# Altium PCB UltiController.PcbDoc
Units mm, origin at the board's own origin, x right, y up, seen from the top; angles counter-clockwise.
Board outline 170 x 47 mm, 2 copper layers (Top Layer, Bottom Layer), stack 1.586 mm thick; 131 components, 59 nets, 314 pads, 147 vias.
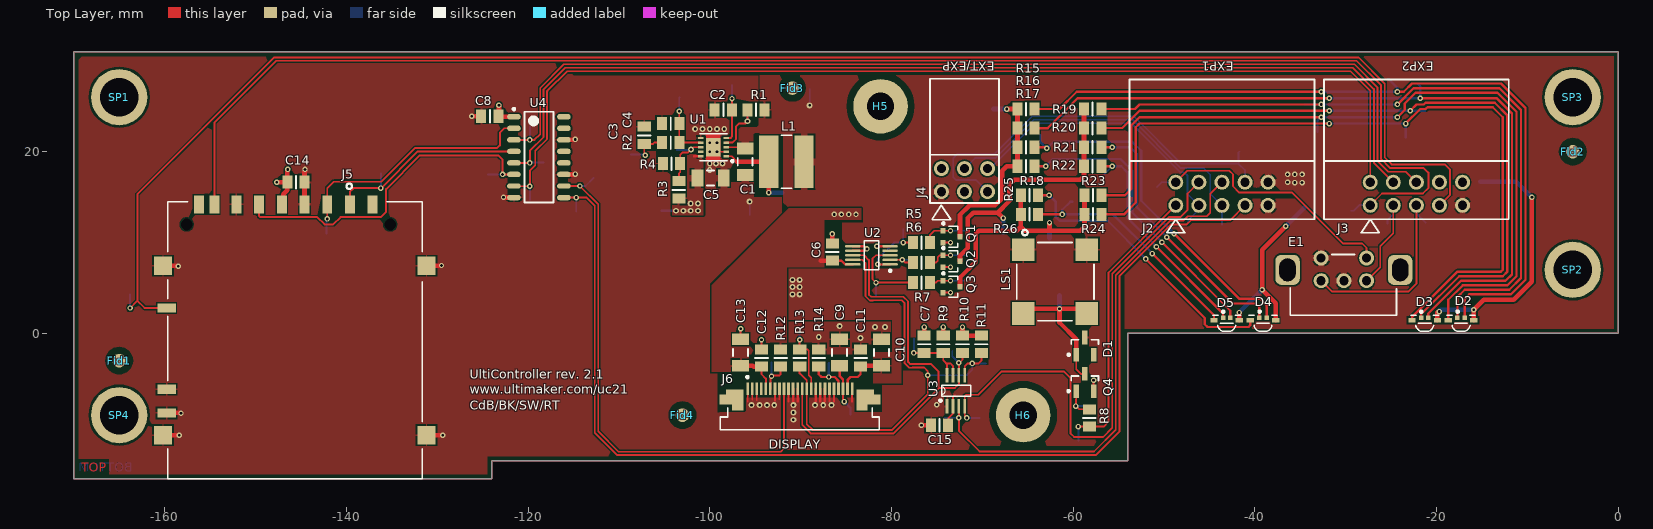
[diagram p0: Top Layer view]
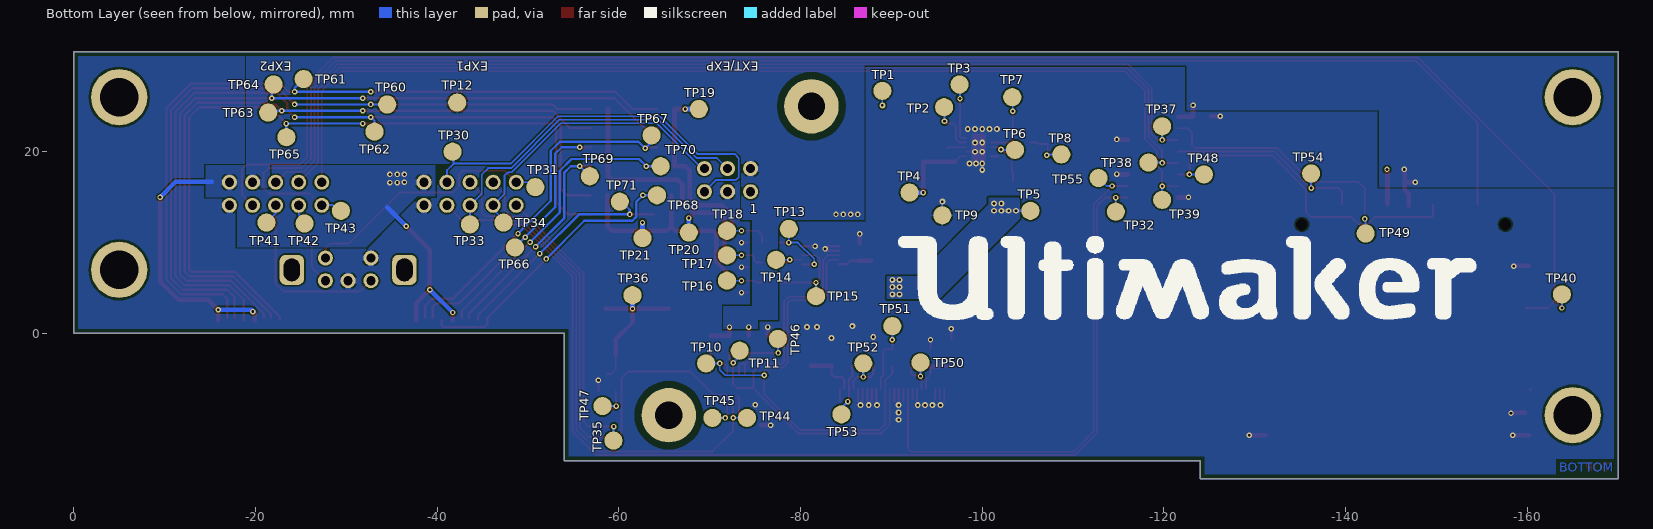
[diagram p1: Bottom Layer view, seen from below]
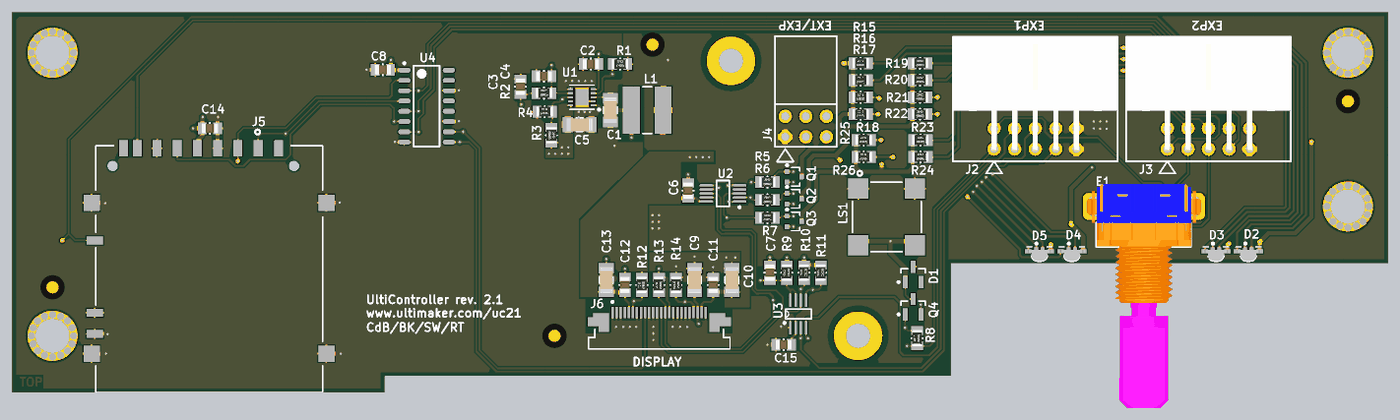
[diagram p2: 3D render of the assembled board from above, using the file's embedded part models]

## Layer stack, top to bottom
Top Layer: signal copper 0.018
Dielectric: core 1.55, FR-4, Dk 4.8
Bottom Layer: signal copper 0.018

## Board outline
-170,-16 -124,-16 -124,-14 -54,-14 -54,0 0,0 0,31 -170,31

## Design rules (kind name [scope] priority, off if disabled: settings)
AssemblyTestPointUsage [All] p1 off:
AssemblyTestpoint [All] p1: testpointundercomponent=FALSE minsize=1.016 maxsize=2.54 preferedsize=1.524 minholesize=0 maxholesize=1.016 preferedholesize=0.813 testpointgrid=0.025 usegrid=TRUE gridtolerance=0 allowsidetop=TRUE allowsidebottom=TRUE
Clearance "Clearance spacers" [(InComponent('SP1')) or (InComponent('SP2'))  or (InComponent('SP3')) or (InComponent('SP4'))] p1: gap=0.254
Clearance "Clearance fiduals" [(InComponent('Fid1'))or (InComponent('Fid2'))or  (InComponent('Fid3'))or  (InComponent('Fid4'))] p2: gap=0.762
Clearance "Clearance mounting holes" [(InComponent('H5')) or (InComponent('H6'))] p3: gap=0.762
Clearance Clearance-xPP-xTP-xTT [All] p4: gap=0.178
ComponentClearance [All] p1: gap=0.25 collisioncheckmode=3 verticalgap=0.25 showdistances=FALSE
DiffPairsRouting [All] p1: maxlimit=0.25 minlimit=0.25 mostfreqgap=0.25 maxuncoupledlength=12.5
FabricationTestPointUsage [All] p1 off: valid=0 allowmultiple=FALSE
Height [All] p1: minheight=0 maxheight=25 prefheight=12.5
HoleSize HoleSize-PTH [All] p1: absolutevalues=TRUE maxlimit=4.3 minlimit=0.25 maxpercent=80.000 minpercent=20.000
HoleToHoleClearance [All] p1: gap=0.15 allowstackedmicrovias=TRUE
MinimumAnnularRing "Minimum IAR  >0.45mm" [((ObjectKind = 'Pad') OR (ObjectKind = 'Via')) And (Layer = 'MultiLayer') And (HoleDiameter > AsMM(0.45))] p1: minimumring=0.25 // minimum inner annular ring for pads > 0.45mm finished hole size
MinimumAnnularRing "Minimum IAR <=0.45mm" [((ObjectKind = 'Pad') OR (ObjectKind = 'Via')) And (Layer = 'MultiLayer') And (HoleDiameter <= AsMM(0.45))] p2: minimumring=0.225 // minimum inner annular ring for pads <= 0.45mm finished hole size
MinimumSolderMaskSliver [All] p1: minsoldermaskwidth=0.1
PlaneClearance PlaneClearance-IPI [All] p1: clearance=0.4
PlaneConnect [All] p1: planeconnectstyle=Relief reliefexpansion=0.4 reliefentries=4 reliefconductorwidth=0.2 reliefairgap=0.2
PolygonConnect "PolygonConnect_ReliefConnect 20mil" [(InComponent('L1'))or (InComponent('C1'))or (InComponent('C5')) or (InComponent('J1'))or(InComponent('J2'))or (InComponent('J3'))or (InComponent('J4'))or (InComponent('E1'))] p1: connectstyle=Relief reliefconductorwidth=0.762 reliefentries=4 polygonreliefangle="90 Angle"
PolygonConnect PolygonConnect_Via [IsVia] p2: connectstyle=Direct reliefconductorwidth=0.254 reliefentries=4 polygonreliefangle="90 Angle"
PolygonConnect PolygonConnect-ReliefConnect [All] p3: connectstyle=Relief reliefconductorwidth=0.2 reliefentries=4 polygonreliefangle="90 Angle"
RoomDefinition Sheet2 [InComponentClass('Sheet2')] p1 off: confinementstyle=ConfineIn formatcopy=TRUE lockcomponents=FALSE outline 101.099,3.499 105.799,3.499 105.799,8.399 101.099,8.399
RoomDefinition Sheet1 [InComponentClass('Sheet1')] p2 off: confinementstyle=ConfineIn formatcopy=TRUE lockcomponents=FALSE outline 101.099,3.499 158.099,3.499 158.099,12.599 101.099,12.599
RoutingCorners [All] p1: cornerstyle=45-Degree minsetback=2.5 maxsetback=2.5
RoutingVias [All] p1: holewidth=0.3 width=0.6 viastyle="Through Hole" minholewidth=0.3 minwidth=0.6 maxholewidth=0.3 maxwidth=0.6
SilkToSilkClearance [All] p1: silktosilkclearance=0.2
SilkscreenOverComponentPads [IsPad] p1: minsilkscreentomaskgap=0.2
SolderMaskExpansion [All] p1: expansion=0.1
Width Width-xTW [All] p1: maxlimit=1.5 minlimit=0.15 preferedwidth=0.2
14 further rules are at their usual default settings.

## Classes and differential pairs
component class Sheet1: C1 C2 C3 C4 C5 C6 D2 D3 D4 D5 Fid1 Fid2 Fid3 Fid4 H2 H5 H6 L1 Q1 Q2 Q3 R1 R2 R3 R4 R5 R6 R7 R15 R16 R17 R18 R19 R20 R21 R22 R23 R24 R25 R26 SP1 SP2 SP3 SP4 TP1 TP2 TP3 TP4 TP5 TP6 TP7 TP8 TP9 TP10 TP11 TP12 TP13 TP14 TP15 TP16 TP17 TP18 TP19 TP20 TP21 TP60 TP61 TP62 TP63 TP64 TP65 TP66 TP67 TP68 TP69 TP70 TP71 U1 U2
component class Sheet2: C7 C8 C9 C10 C11 C12 C13 C14 C15 D1 E1 J2 J3 J4 J5 J6 LS1 Q4 R8 R9 R10 R11 R12 R13 R14 TP30 TP31 TP32 TP33 TP34 TP35 TP36 TP37 TP38 TP39 TP40 TP41 TP42 TP43 TP44 TP45 TP46 TP47 TP48 TP49 TP50 TP51 TP52 TP53 TP54 TP55 U3 U4

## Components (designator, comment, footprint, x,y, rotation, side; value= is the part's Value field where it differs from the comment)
C1 "4.7uF" "C1206 (3216)" -96.1,18.9 r90 top
C2 "10nF" "C0805 (2012)" -98.5,24.6 r0 top
C3 "2.2nF" "C0805 (2012)" -107.2,21.8 r270 top
C4 "15pF" "C0805 (2012)" -104.3,23.1 r0 top
C5 "10uF" "C1206 (3216)" -99.9,17.1 r180 top
C6 "100nF" "C0805 (2012)" -86.5,8.95 r90 top
C7 "10nF" "C0805 (2012)" -76.4,-1.2 r270 top
C8 "100nF" "C0805 (2012)" -124.2,23.9 r0 top
C9 "4.7uF" "C1206 (3216)" -85.7,-2.1 r90 top
C10 "10uF" "C1206 (3216)" -81.1,-2.1 r270 top
C11 "100nF" "C0805 (2012)" -83.4,-2.7 r270 top
C12 "100nF" "C0805 (2012)" -94.3,-2.7 r270 top
C13 "4.7uF" "C1206 (3216)" -96.6,-2.1 r90 top
C14 "100nF" "C0805 (2012)" -145.55,16.65 r180 top
C15 "100nF" "C0805 (2012)" -74.7,-10.1 r0 top
D1 "BAS16" "IC SOT23" -58.7,-1.4 r90 top
D2 "LED 598-8810-307F" "LED SMD  598-8810-307F" -17.7,1.7 r180 top
D3 "LED 598-8810-307F" "LED SMD  598-8810-307F" -21.7,1.7 r180 top
D4 "LED 598-8810-307F" "LED SMD  598-8810-307F" -39.5,1.7 r180 top
D5 "LED 598-8810-307F" "LED SMD  598-8810-307F" -43.5,1.7 r180 top
E1 "EC11B15242AE" "MISC EC11B15242AE" -32.7,5.8 r270 top locked
Fid1 "Fiducial" "FIDUCIAL 1,5MM"#1 -162,-3 r180 top
Fid2 "Fiducial" "FIDUCIAL 1,5MM"#2 -5,20 r270 top
Fid3 "Fiducial" "FIDUCIAL 1,5MM"#2 -90.9,27 r270 top
Fid4 "Fiducial" "FIDUCIAL 1,5MM"#2 -103,-9 r270 top
H5 "3mm" "MOUNTING HOLE 3MM PTH" -81.2,25 r90 top
H6 "3mm" "MOUNTING HOLE 3MM PTH" -65.5,-9 r0 top
J2 "10p" "HEADER 10P RIGHT ANGLE" -48.7,14.1 r0 top locked
J3 "10p" "HEADER 10P RIGHT ANGLE" -27.3,14.1 r0 top locked
J4 "6p" "HEADER 6P RIGHT ANGLE" -74.5,15.6 r0 top
J5 "SD Memory Card connector" "CON SD-CARD" -139.6,14.2 r0 top locked
J6 "SFV24R-1STE9LF" "CON SFV24R-1STE9LF" -95.823,-6.1 r0 top
L1 "4.7uH" "INDUCTOR MCSDC0604" -89.6,18.9 r90 top
LS1 "KSSGJ4B20" "BUZZER KSSGJ4B20" -65.5,9.2 r270 top
Q1 "PBSS4140U" "IC SOT323" -74.3,11.3 r180 top
Q2 "PBSS4140U" "IC SOT323" -74.3,8.6 r180 top
Q3 "PBSS4140U" "IC SOT323" -74.3,5.8 r180 top
Q4 "MMBT3904" "IC SOT23" -58.7,-5.4 r90 top
R1 "10K" "R0805 (2012)" -94.9,24.6 r0 top
R2 "46.4K" "R0805 (2012)" -104.3,21 r0 top
R3 "191K" "R0805 (2012)" -103.4,15.8 r270 top
R4 "20.5K" "R0805 (2012)" -104.2,18.7 r0 top
R5 "330E" "R0805 (2012)" -76.7,10 r0 top
R6 "330E" "R0805 (2012)" -76.7,7.8 r0 top
R7 "330E" "R0805 (2012)" -76.7,5.6 r0 top
R8 "330E" "R0805 (2012)" -58.2,-9.3 r90 top
R9 "191K" "R0805 (2012)" -74.3,-1.2 r90 top
R10 "4.7K" "R0805 (2012)" -72.175,-1.2 r90 top
R11 "4.7K" "R0805 (2012)" -70.1,-1.2 r90 top
R12 "10K" "R0805 (2012)" -92.2,-2.7 r90 top
R13 "0E" "R0805 (2012)" -90.1,-2.7 r90 top
R14 "1M" "R0805 (2012)" -88,-2.7 r270 top
R15 "150E" "R0805 (2012)" -65.178,24.697 r0 top
R16 "150E" "R0805 (2012)" -65.178,22.597 r0 top
R17 "150E" "R0805 (2012)" -65.178,20.497 r0 top
R18 "150E" "R0805 (2012)" -65.178,18.397 r0 top
R19 "100E" "R0805 (2012)" -57.85,24.7 r0 top
R20 "100E" "R0805 (2012)" -57.85,22.6 r0 top
R21 "100E" "R0805 (2012)" -57.85,20.5 r0 top
R22 "100E" "R0805 (2012)" -57.85,18.4 r0 top
R23 "100E" "R0805 (2012)" -57.8,15.2 r0 top
R24 "100E" "R0805 (2012)" -57.8,13.1 r0 top
R25 "100E" "R0805 (2012)" -64.8,15.2 r0 top
R26 "100E" "R0805 (2012)" -64.8,13.1 r0 top
SP1 "M3-10ET" "SPACER M3-10ET" -165,26 r0 top locked
SP2 "M3-10ET" "SPACER M3-10ET" -5,7 r0 top locked
SP3 "M3-10ET" "SPACER M3-10ET" -5,26 r0 top locked
SP4 "M3-10ET" "SPACER M3-10ET" -165,-9 r0 top locked
TP1 "2mm" "TESTPOINT 2MM" -89,26.7 r270 bottom
TP2 "2mm" "TESTPOINT 2MM" -95.8,24.9 r90 bottom
TP3 "2mm" "TESTPOINT 2MM" -97.5,27.4 r90 bottom
TP4 "2mm" "TESTPOINT 2MM" -92,15.5 r90 bottom
TP5 "2mm" "TESTPOINT 2MM" -105.3,13.5 r90 bottom
TP6 "2mm" "TESTPOINT 2MM" -103.6,20.2 r90 bottom
TP7 "2mm" "TESTPOINT 2MM" -103.3,26 r90 bottom
TP8 "2mm" "TESTPOINT 2MM" -108.7,19.7 r90 bottom
TP9 "2mm" "TESTPOINT 2MM" -95.6,13 r0 bottom
TP10 "2mm" "TESTPOINT 2MM" -69.6,-3.3 r90 bottom
TP11 "2mm" "TESTPOINT 2MM" -73.3,-1.9 r90 bottom
TP12 "2mm" "TESTPOINT 2MM" -42.2,25.4 r90 bottom
TP13 "2mm" "TESTPOINT 2MM" -78.7,11.5 r90 bottom
TP14 "2mm" "TESTPOINT 2MM" -77.3,8.1 r90 bottom
TP15 "2mm" "TESTPOINT 2MM" -81.7,4.1 r90 bottom
TP16 "2mm" "TESTPOINT 2MM" -71.9,5.8 r90 bottom
TP17 "2mm" "TESTPOINT 2MM" -71.9,8.6 r90 bottom
TP18 "2mm" "TESTPOINT 2MM" -71.9,11.3 r90 bottom
TP19 "2mm" "TESTPOINT 2MM" -68.8,24.7 r90 bottom
TP20 "2mm" "TESTPOINT 2MM" -67.7,11.1 r90 bottom
TP21 "2mm" "TESTPOINT 2MM" -62.6,10.5 r90 bottom
TP30 "2mm" "TESTPOINT 2MM" -41.7,20 r90 bottom
TP31 "2mm" "TESTPOINT 2MM" -50.8,16.1 r0 bottom
TP32 "2mm" "TESTPOINT 2MM" -114.7,13.4 r90 bottom
TP33 "2mm" "TESTPOINT 2MM" -43.6,12 r90 bottom
TP34 "2mm" "TESTPOINT 2MM" -47.3,12.2 r90 bottom
TP35 "2mm" "TESTPOINT 2MM" -59.4,-11.8 r0 bottom
TP36 "2mm" "TESTPOINT 2MM" -61.5,4.2 r90 bottom
TP37 "2mm" "TESTPOINT 2MM" -119.8,22.8 r90 bottom
TP38 "2mm" "TESTPOINT 2MM" -118.3,18.8 r90 bottom
TP39 "2mm" "TESTPOINT 2MM" -119.8,14.7 r90 bottom
TP40 "2mm" "TESTPOINT 2MM" -163.8,4.3 r90 bottom
TP41 "2mm" "TESTPOINT 2MM" -21.2,12.2 r0 bottom
TP42 "2mm" "TESTPOINT 2MM" -25.4,12.1 r0 bottom
TP43 "2mm" "TESTPOINT 2MM" -29.4,13.5 r90 bottom
TP44 "2mm" "TESTPOINT 2MM" -74.1,-9.3 r0 bottom
TP45 "2mm" "TESTPOINT 2MM" -70.3,-9.3 r0 bottom
TP46 "2mm" "TESTPOINT 2MM" -77.5,-0.6 r90 bottom
TP47 "2mm" "TESTPOINT 2MM" -58.2,-8 r90 bottom
TP48 "2mm" "TESTPOINT 2MM" -124.4,17.5 r90 bottom
TP49 "2mm" "TESTPOINT 2MM" -142.2,11 r90 bottom
TP50 "2mm" "TESTPOINT 2MM" -93.2,-3.2 r90 bottom
TP51 "2mm" "TESTPOINT 2MM" -90.1,0.8 r90 bottom
TP52 "2mm" "TESTPOINT 2MM" -86.9,-3.3 r90 bottom
TP53 "2mm" "TESTPOINT 2MM" -84.5,-8.9 r90 bottom
TP54 "2mm" "TESTPOINT 2mm" -136.2,17.6 r270 bottom
TP55 "2mm" "TESTPOINT 2mm" -112.8,17.1 r270 bottom
TP60 "2mm" "TESTPOINT 2mm" -34.5,25.2 r270 bottom
TP61 "2mm" "TESTPOINT 2mm" -25.3,28 r270 bottom
TP62 "2mm" "TESTPOINT 2mm" -33.1,22.2 r270 bottom
TP63 "2mm" "TESTPOINT 2mm" -21.4,24.3 r270 bottom
TP64 "2mm" "TESTPOINT 2mm" -22,27.4 r270 bottom
TP65 "2mm" "TESTPOINT 2mm" -23.4,21.6 r270 bottom
TP66 "2mm" "TESTPOINT 2mm" -48.563,9.463 r270 bottom
TP67 "2mm" "TESTPOINT 2mm" -63.6,21.8 r270 bottom
TP68 "2mm" "TESTPOINT 2mm" -64.2,15.2 r270 bottom
TP69 "2mm" "TESTPOINT 2mm" -56.8,17.3 r270 bottom
TP70 "2mm" "TESTPOINT 2mm" -64.6,18.4 r270 bottom
TP71 "2mm" "TESTPOINT 2mm" -60.1,14.5 r270 bottom
U1 "IC LM4510SD/NOPB" "IC SDA10A" -98.2,19.5 r90 top
U2 "PCA9632DP2" "IC TSSOP-10" -82.2,8.6 r180 top
U3 "PCA9306" "IC SSOP-8" -73.875,-8 r0 top
U4 "74HC4050D" "IC SOIC-16" -118.8,19.4 r0 top

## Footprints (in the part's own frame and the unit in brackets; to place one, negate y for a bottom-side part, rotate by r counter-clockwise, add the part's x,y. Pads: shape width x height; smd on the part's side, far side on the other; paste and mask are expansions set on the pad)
"BUZZER KSSGJ4B20" [mm] "Buzzer KSSGJ4B20 SMD"
  rect 2.5x2.5 smd: 1(0,0) 2(0,7) 3(7,7) 4(7,0)
  silkscreen extent -2.2,-0.7 7.8,7.8, body extent -0.75,-0.7 7.75,7.8, height 3.2
"C0805 (2012)" [mm] "hip Capacitor, 2-Leads, Body 2,0x1.25mm, IPC Medium Density"
  rect 1.1x1.45 smd: 1(-0.95,0) 2(0.95,0)
  silkscreen extent 0,-0.7 0,0.7, body extent -1,-0.6 1,0.6, height 1.19
"C1206 (3216)" [mm] "Chip Capacitor, 2-Leads, Body 3.2x1.6mm, IPC Medium Density"
  rect 1.3x1.85 smd: 1(-1.45,0) 2(1.45,0)
  silkscreen extent -0.4,-0.82 0.4,0.82, body extent -1.6,-0.8 1.6,0.8, height 0.77
"CON SD-CARD" [mm] "Std,reverse SD Memory Card connector SMD"
  round 0 hole 1.3 unplated: 0(-17.975,-2.2) 0(4.425,-2.2)
  rect 1.1x2 smd: 1(0,0) 2(-2.5,0) 3(-5,0) 4(-7.5,0) 5(-10,0) 6(-12.5,0) 7(-14.925,0) 8(-16.625,0) 9(2.5,0)
  rect 2x1 smd: 10(-20.175,-11.4) 11(-20.175,-20.35) 12(-20.175,-22.95)
  rect 2x2 smd: A(8.425,-6.75) B(8.425,-25.4) C(-20.575,-6.75) D(-20.575,-25.4)
  silkscreen extent -20.05,-30.2 7.95,2.3, body extent -20.05,-30.2 7.95,0.3, height 2.9
"CON SFV24R-1STE9LF" [mm] "Connnector SFV24R-1STE9LF 24 pins SMD"
  rect 0.7x1.1 smd: 0(-2.75,-1.15) 0(14.25,-1.15)
  rect 1.95x1.6 smd: 0(-1.43,-0.9) 0(12.93,-0.9)
  rect 1.25x0.7 smd: 0(-1.08,-2.05) 0(12.58,-2.05)
  rect 0.3x1.4 smd: 1(0,0) 2(0.5,0) 3(1,0) 4(1.5,0) 5(2,0) 6(2.5,0) 7(3,0) 8(3.5,0) 9(4,0) 10(4.5,0) 11(5,0) 12(5.5,0) 13(6,0) 14(6.5,0) 15(7,0) 16(7.5,0) 17(8,0) 18(8.5,0) 19(9,0) 20(9.5,0) 21(10,0) 22(10.5,0) 23(11,0) 24(11.5,0)
  silkscreen extent -3,-4.5 14.5,1.42, body extent -3,-4.5 14.5,-0.3, height 1.8
"FIDUCIAL 1,5MM"#1 [mm] "Fiducial 1,5mm"
  round 1.5 smd paste-3 mask+0.75: ""(3,0)
"FIDUCIAL 1,5MM"#2 [mm] "Fiducial 1,5mm"
  round 1.5 smd paste-3 mask+0.75: ""(0,0)
"HEADER 6P RIGHT ANGLE" [mm] "Header 2x3p right angle 2.54mm"
  round 1.65 hole 1.02: 1(0,0) 2(0,2.54) 3(2.54,0) 4(2.54,2.54) 5(5.08,0) 6(5.08,2.54)
  silkscreen extent -1.27,-3.08 6.35,12.44, body extent -1.27,-1.27 6.35,12.44, height 4.83
"HEADER 10P RIGHT ANGLE" [mm] "Header 2x5p right angle 2.54mm"
  round 1.65 hole 1.02: 1(0,0) 2(0,2.54) 3(2.54,0) 4(2.54,2.54) 5(5.08,0) 6(5.08,2.54) 7(7.62,0) 8(7.62,2.54) 9(10.16,0) 10(10.16,2.54)
  silkscreen extent -5.09,-3.02 15.26,13.86, body extent -5.08,-0.32 15.24,13.86, height 8.8
"IC SDA10A" [mm] "SON- 10-Leads, Body 3x3mm, Pitch 0.5mm"
  rect 0.25x0.6 smd paste+0: 1(0,0) 2(0.5,0) 3(1,0) 4(1.5,0) 5(2,0) 6(2,2.8) 7(1.5,2.8) 8(1,2.8) 9(0.5,2.8) 10(0,2.8)
  rect 2x1.6 smd paste+0: 11(1,1.4)
  silkscreen extent -0.65,-0.83 2.5,2.9, body extent -0.5,-0.1 2.5,2.9, height 0.8
"IC SOIC-16" [mm] "SOIC, 16-Leads, Body 9.9x3.9mm, Pitch 1.27mm, IPC Medium Density"
  oval 1.5x0.6 smd: 1(-2.75,4.445) 2(-2.75,3.175) 3(-2.75,1.905) 4(-2.75,0.635) 5(-2.75,-0.635) 6(-2.75,-1.905) 7(-2.75,-3.175) 8(-2.75,-4.445) 9(2.75,-4.445) 10(2.75,-3.175) 11(2.75,-1.905) 12(2.75,-0.635) 13(2.75,0.635) 14(2.75,1.905) 15(2.75,3.175) 16(2.75,4.445)
  silkscreen extent -2.87,-5 1.6,5.42, body extent -2,-5 2,5, height 1.73
"IC SOT23" [mm] "SOT23, 3-Leads, Body 2.9x1.3mm, Pitch 0.95mm, Lead Span 2.5mm, IPC Medium Density"
  rect 1.5x0.6 smd: 1(-0.95,0.95) 2(-0.95,-0.95) 3(0.95,0)
  silkscreen extent -1.07,-1.5 0.7,1.92, body extent -0.7,-1.5 0.7,1.5, height 1.1
"IC SOT323" [mm] "IC SOT323"
  rect 0.55x0.6 smd paste+0: 1(0,0) 2(0,1.3) 3(-1.85,0.65)
  silkscreen extent -1.6,-0.92 0.1,1.8, body extent -1.6,-0.5 -0.2,1.8, height 1.1
"IC SSOP-8" [mm] "IC SSOP-8 SMD"
  rect 0.3x1.6 smd paste+0: 1(0,0) 2(0.65,0) 3(1.3,0) 4(1.95,0) 5(1.95,3.4) 6(1.3,3.4) 7(0.65,3.4) 8(0,3.4)
  silkscreen extent -0.85,0.48 2.6,2.3, body extent -0.6,0.3 2.6,3.2, height 1.3
"IC TSSOP-10" [mm] "TSSOP, 10-Leads, Body 3x3mm, Pitch 0.5mm, IPC Medium Density"
  oval 1.7x0.3 smd: 1(-2.05,1) 2(-2.05,0.5) 3(-2.05,0) 4(-2.05,-0.5) 5(-2.05,-1) 6(2.05,-1) 7(2.05,-0.5) 8(2.05,0) 9(2.05,0.5) 10(2.05,1)
  silkscreen extent -2.17,-1.6 0.8,1.82, body extent -1.6,-1.6 1.6,1.6, height 1.1
"INDUCTOR MCSDC0604" [mm] "Inductor MCSDC0604"
  rect 5.8x2.1 smd paste+0: 1(0,0) 2(0,3.9)
  silkscreen extent -2.9,1.4 2.9,2.5, body extent -2.9,-1 2.9,4.9, height 1.8
"LED SMD  598-8810-307F" [mm] "LED tricolor SMD"
  rect 0.5x0.5 smd: 1(0,0) 2(-0.8,0)
  rect 0.8x0.5 smd: 3(1,0.25) 4(-1.8,0.25)
  silkscreen extent -1.95,-0.82 1.15,1.48, body extent -2,0.05 1.2,1.46, height 0.99
"MISC EC11B15242AE" [mm] "Misc EC11B15242AE encoder"
  rrect50% 3.3x2.7 hole 1.8 slot 2.5 at 0 deg: 0(-1.2,8.7) 0(-1.2,-3.7)
  round 1.65 hole 1: A(0,0) B(0,5) C(0,2.5) D(-2.5,0) E(-2.5,5)
  silkscreen extent -2.9,-3.4 3.8,8.3, body extent -4,-4.55 23.75,9.55, height 13.79
"MOUNTING HOLE 3MM PTH" [mm] "Mounting Hole 3mm PTH"
  round 6 hole 3: 0(0,0)
"R0805 (2012)" [mm] "hip Resistor, 2-Leads, Body 2,0x1.25mm, IPC Medium Density"
  rect 1.1x1.45 smd: 1(-0.95,0) 2(0.95,0)
  silkscreen extent 0,-0.7 0,0.7, body extent -1,-0.6 1,0.65, height 0.44
"SPACER M3-10ET" [mm] "Spacer M3-10ET"
  round 6.2 hole 4.22: 0(0,0)
"TESTPOINT 2MM" [mm] "TESTPOINT 2mm"
  round 2 smd paste-2 mask+0: 1(0,0)
"TESTPOINT 2mm" [mm] "TESTPOINT 2mm"
  round 2 smd paste-2 mask+0: 1(0,0)

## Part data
C1 C9 C13: library part "Cap 4.7uF X7R 1206", "Cap 4.7uF 1206 X7R 10% 25V"
C2 C7: library part "Cap 10nF X7R 0805", "Cap 10nF X7R 0805 10% 100V"
C3: library part "Cap 2.2nF X7R 0805", "Cap 2.2nF X7R 0805 10% 100V"
C4: library part "Cap 15pF NPO 0805", "Cap 15pF NPO 0805 5% 100V"
C5 C10: library part "Cap 10uF X7R 1206", "Cap 10uF 1206 X7R 10% 25V"
C6 C8 C11 C12 C14 C15: library part "Cap 100nF X7R 0805", "Cap 100nF X7R 0805 10% 100V"
D1: library part "Diode BAS16", "Diode BAS16  SOT23 85V 215MA"
D2 D3 D4 D5: "LED MULTICOLOR RED/GRN/BLUE 1208"
E1: library part "Misc EC11B15242AE", "Misc EC11B15242AE encoder horiz"
H5 H6: "Mounting Hole 3mm PTH"
J2 J3: "Header 2x5p right angle 2.54mm"
J4: "Header 2x3p right angle 2.54mm"
J5: "Connector Std,reverse SD Memory Card connector"
J6: library part "Connector SFV24R-1STE9LF", "Connector FPC/FFC 0.5mm R/A 24p SMD"
L1: library part "Inductor 4.7uH SMD", "Inductor 4.7uH SMD"
LS1: library part "Buzzer KSSGJ4B20", "Buzzer KSSGJ4B20 SMD"
Q1 Q2 Q3: library part "NPN PBSS4140U", "NPN PBSS4140U SOT-323 1A"
Q4: library part "NPN MMBT3904", "NPN MMBT3904 SOT-23 200mA"
R1 R12: library part "Res 10K 0805", "Res 10K 0805 1% 100mW"
R2: library part "Res 46.4K 0805", "Res 46.4K 0805 1% 100mW"
R3 R9: library part "Res 191K 0805", "Res 191K 0805 1% 125mW"
R4: library part "Res 20.5K 0805", "Res 20.5K 0805 1% 100mW"
R5 R6 R7 R8: library part "Res 330E 0805", "Res 330E 0805 1% 100mW"
R10 R11: library part "Res 4.7K 0805", "Res 4.7K 0805 1% 100mW"
R13: library part "Res 0E 0805", "Res 0E 0805 1% 100mW"
R14: library part "Res 1M 0805", "Res 1M 0805 1% 100mW"
R15 R16 R17 R18: library part "Res 150E 0805", "Res 150E 0805 1% 125mW"
R19 R20 R21 R22 R23 R24 R25 R26: library part "Res 100E 0805", "Res 100E 0805 1% 125mW"
SP1 SP2 SP3 SP4: "Spacer SMTSO-M3-10ET"
TP1 TP2 TP3 TP4 TP5 TP6 TP7 TP8 TP9 TP10 TP11 TP12 TP13 TP14 TP15 TP16 TP17 TP18 TP19 TP20 TP21 TP30 TP31 TP32 TP33 TP34 TP35 TP36 TP37 TP38 TP39 TP40 TP41 TP42 TP43 TP44 TP45 TP46 TP47 TP48 TP49 TP50 TP51 TP52 TP53 TP54 TP55 TP60 TP61 TP62 TP63 TP64 TP65 TP66 TP67 TP68 TP69 TP70 TP71: "Testpoint, 2mm, round"
U1: "IC Synchronous Step-Up DC/DC Converter with True Shutdown Isolation, 10-pin LLP, Pb-Free"
U2: library part "IC PCA9632", "IC LED DRIVER RGBA"
U3: library part "IC PCA9306", "IC PCA9306 Voltage Level translator"
U4: library part "IC 74HC4050D", "IC Hex Non-Inverting Buffer/Logic-Level Down Converter"

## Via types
v1: diameter 0.6, hole 0.3, Top Layer to Bottom Layer, tented both sides, 74 vias
v2: diameter 0.65, hole 0.3, Top Layer to Bottom Layer, tented both sides, 40 vias
v3: diameter 0.6, hole 0.3, Top Layer to Bottom Layer, 29 vias
v4: diameter 0.65, hole 0.3, Top Layer to Bottom Layer, 4 vias

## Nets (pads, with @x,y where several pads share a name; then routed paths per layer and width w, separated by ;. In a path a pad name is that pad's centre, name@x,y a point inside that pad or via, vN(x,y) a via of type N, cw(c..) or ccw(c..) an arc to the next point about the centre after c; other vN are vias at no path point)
3.3V: C6.1 C8.2 C12.2 C13.1 C14.2 J3.8 J4.2 J5.4 J6.5 R9.2 R10.2 R11.2 R12.2 TP12.1 U2.10 U4.1 | length 21
  Top Layer w0.203: C12.2 -94.3,-4.5 -93.823,-4.977 J6.5
  Top Layer w0.254: C6.1@-86.45,7.95 C6.1 -85.493,8 -85.093,7.6 U2.10
  Top Layer w0.508: v1(-147.65,16.65) C14.2 ; J5.4@-146.95,14.05 -146.95,15.329 -146.5,15.779 C14.2 ; v1@-146.45,17.95 -146.5,17.9 C14.2 ; v1(-123.2,25.1) -123.2,23.95 C8.2 -123.195,23.845 U4.1 ; C13.1 -95.25,-3.55 -95.15,-3.65 C12.2 ; -87.8,8 C6.1 ; R9.2 v1(-74.3,0.7) ; v1(-72.175,0.7) R10.2 R11.2
  other v1: -86.3,13.1 -85.5,13.1 -84.7,13.1 -83.9,13.1 -146.45,18.05
5V: C1.2 C15.2 D1.3 D2.4 D3.4 D4.4 D5.4 J2.10 J3.10 J4.1 L1.1 LS1.1 LS1.2 R1.2 TP1.1 U1.3 U3.2 | length 56.7
  Top Layer w0.203: U1.3 -96.25,20.5 C1.2 ; C15.2 -73.75,-9.35 -73.225,-8.825 U3.2 -73.225,-7.025 -73,-6.8
  Top Layer w0.508: D5.4 v3(-41.7,2.3) ; D4.4 -37.7,3.3 v3(-39.2,4.8) -39.2,9.2 v1(-36.6,11.8) ; D3.4 -19.9,2.3 -19.8,2.4 v3(-19.7,2.4) ; D2.4 v3(-15.9,2.6) -14.8,3.7 -11.5,3.7 -9.5,5.7 v3(-9.5,15)
  Bottom Layer w0.2: v2(-89,25.1) TP1.1@-89,26.9
  Bottom Layer w0.508: v3(-41.7,2.3) v3(-39.2,4.8) ; v1(-36.6,11.8) -34.5,13.9 ; v3(-19.7,2.4) -19.8,2.4 -19.6,2.6 v3(-15.9,2.6) ; -15.2,16.7 -11.2,16.7 v3(-9.5,15)
  other v1: -35.6,16.6 -34.8,16.6 -36.4,16.64 -36.4,17.5 -35.6,17.5 -34.8,17.5
13V: C5.2 C10.2 C11.2 J6.23 R3.2 TP5.1 U1.10 | length 8.1
  Top Layer w0.254: -101.7,19.5 U1.10 ; J6.23 -84.823,-5.123 -84.5,-4.8 -83.7,-4.8 -83.4,-4.5 C11.2
  Top Layer w0.508: C11.2 -83.3,-3.55 C10.2
  Bottom Layer w0.254: TP5.1 v2(-103.7,13.5)
  other v2: -90.9,4.3 -90.1,4.3 -90.9,5.1 -90.1,5.1 -90.9,5.9 -90.1,5.9 -102.9,13.5 -102.1,13.5 -101.3,13.5 -102.1,14.3 -101.3,14.3
BLUE1: D2.3 R23.2 TP62.1 | length 86.4
  Top Layer w0.254: R23.2 -54.3,15.2 -53.6,15.9 -53.6,22.9 -52.7,23.8 v3(-32.7,23.8) ; v3(-24.3,23.8) -23.5,24.6 -23.5,25.3 -22.295,26.505 -13.305,26.505 -11.2,24.4 -11.2,6.3 -12.2,5.3 -17.1,5.3 -18.7,3.7 D2.3
  Bottom Layer w0.254: TP62.1 -33.1,23.4 v3(-32.7,23.8) v3(-24.3,23.8)
BLUE2: D3.3 R24.2 TP65.1 | length 85.2
  Top Layer w0.254: R24.2 -54.4,13.1 -53.1,14.4 -53.1,22.7 -52.7,23.1 v3(-31.8,23.1) ; v3(-23.4,23.1) -21.8,24.7 -21.2,24.7 -21,24.9 -13.8,24.9 -12.7,23.8 -12.7,7 -12.9,6.8 -17.7,6.8 -22.7,1.8 D3.3
  Bottom Layer w0.254: v3(-31.8,23.1) v3(-23.4,23.1) TP65.1
BLUE3: D4.3 R25.2 TP68.1 | length 32.9
  Top Layer w0.254: R25.2 v3(-62.65,15.2) ; v3(-52,8.2) -45.5,1.7 -45.5,1 -45.2,0.7 -40.7,0.7 -40.5,0.9 D4.3
  Bottom Layer w0.254: TP68.1 v3(-62.65,15.2) -61.9,14.45 -61.9,12.8 -61.5,12.4 -56.2,12.4 v3(-52,8.2)
BLUE4: D5.3 R26.2 TP71.1 | length 26.5
  Top Layer w0.254: R26.2 v3(-61.2,13.1) ; v1(-51.291,8.791) -44.5,2 D5.3
  Bottom Layer w0.254: TP71.1 -60.3,14.5 -61.2,13.6 v3(-61.2,13.1) -55.6,13.1 v1(-51.291,8.791)
GND: C1.1 C2.1 C3.1 C4.1 C5.1 C6.2 C7.1 C8.1 C9.2 C10.1 C11.1 C12.1 C13.2 C14.1 C15.1 E1.C E1.D J2.9 J3.9 J4.3 J5.3 J5.6 J5.11 J5.12 J5.A J5.B J5.C J5.D J6.1 J6.2 J6.3 J6.7 J6.8 J6.10 J6.11 J6.12 J6.16 J6.17 J6.18 J6.19 J6.20 J6.24 Q1.2 Q2.2 Q3.2 Q4.2 R4.1 R14.1 TP9.1 U1.2 U1.6 U1.11 U2.5 U2.6 U2.7 U3.1 U4.8 U4.11 U4.14 | length 51.5
  Top Layer w0.203: U1.11@-99.1,20 U1.2 ; C13.2 v1(-96.6,0.5) ; -95.823,-7.477 J6.1 ; -95.323,-7.277 J6.2 ; -94.823,-7.323 J6.3 ; C12.1 v1(-94.3,-0.7) ; -92.823,-7.416 J6.7 ; -92.323,-7.223 J6.8 ; -84.323,-7.5 J6.24 ; Q3.2 v1(-73.5,4.5) ; Q2.2 v1(-73.5,7.3) ; Q1.2 v1(-73.5,10) ; Q4.2 v1(-57.75,-5.15)
  Top Layer w0.254: J5.11@-160.375,-6.15 J5.11@-160.325,-6.2 ; J5.12@-158.85,-8.75 J5.12@-158.8,-8.8 ; -91.323,-7.477 J6.10 ; -90.823,-7.477 J6.11 ; -90.323,-7.477 J6.12 ; -88.323,-7.477 J6.16 ; -87.823,-7.477 J6.17 ; -87.323,-7.477 J6.18 ; -86.823,-7.477 J6.19 ; -86.323,-7.477 J6.20 ; U2.7 -82.9,9.1 v1(-82.7,9.3) -83,9.6 U2.6 ; v1(-81.6,9.6) U2.5
  Top Layer w0.508: J5.D v1(-158.4,-11.2) ; J5.C -158.55,7.45 v1(-158.5,7.4) ; J5.12 v1@-158.25,-8.75 ; J5.3 C14.1 -144.6,17.8 v1@-144.55,17.85 ; J5.B v1(-129.4,-11.2) ; J5.A v1@-129.65,7.45 ; v1(-126.2,23.9) C8.1 ; v1(-122.7,15) -122.655,14.955 U4.8 ; U4.11 -114.845,17.495 v1(-114.8,17.54) ; U4.14 -114.845,21.305 v1(-114.8,21.35) ; C6.2 v1(-86.5,10.95) ; v1(-76.7,-10.1) C15.1 ; C7.1 v1(-76.4,0.7)
  Bottom Layer w0.203: TP9.1 v2(-95.6,14.5)
  other v1: -158.2,-8.8 -75.007,-7.857 -129.525,7.475 -144.55,18.05
  other v2: -90.8,-9.5 -90.8,-8.7 -95.4,-7.9 -94.5,-7.9 -93.7,-7.9 -92.9,-7.9 -90.8,-7.9 -88.4,-7.9 -87.5,-7.9 -86.6,-7.9 -83.4,-0.5 -88,-0.4 -81.8,0.7 -80.7,0.7 -85.7,0.8 -100,18 -100,18.7 -99.3,18.7 -98.6,18.7 -101.6,22.5 -100.8,22.5 -100,22.5 -99.2,22.5 -98.4,22.5
  other v4: -100,20 -99.2,20 -100,21 -99.2,21
GREEN1: D2.1 R19.2 TP60.1 | length 78.6
  Top Layer w0.254: R19.2 -53.2,24.7 -52.7,25.2 v3(-32.7,25.2) ; v3(-24.3,25.2) -22.5,27 -13.1,27 -10.7,24.6 -10.7,6.1 -12,4.8 -16.9,4.8 -17.7,4 D2.1
  Bottom Layer w0.254: TP60.1 v3(-32.7,25.2) v3(-24.3,25.2)
GREEN2: D3.1 R20.2 TP63.1 | length 77.1
  Top Layer w0.254: R20.2 -54.6,22.6 -52.7,24.5 v3(-31.8,24.5) ; v3(-22.9,24.5) -22.2,25.2 -21.4,25.2 -21.2,25.4 -13.6,25.4 -12.2,24 -12.2,6.8 -12.7,6.3 -17.5,6.3 -21.7,2.1 D3.1
  Bottom Layer w0.254: v3(-31.8,24.5) v3(-22.9,24.5) TP63.1@-21.3,24.5
GREEN3: D4.1 R21.2 TP66.1 | length 31.4
  Top Layer w0.254: R21.2 v3(-55.7,20.5) ; v1(-49.7,10.6) -42.4,3.3 -39.9,3.3 -39.5,2.9 D4.1
  Bottom Layer w0.254: v3(-55.7,20.5) -53.7,20.5 -53,19.8 -53,13.9 v1(-49.7,10.6) -48.3,9.2 TP66.1@-48.2,9.2
GREEN4: D5.1 R22.2 TP69.1 | length 25.1
  Top Layer w0.254: R22.2 v3(-55.7,18.4) ; v1(-50.831,9.531) -43.5,2.2 D5.1
  Bottom Layer w0.254: TP69.1 v3(-55.7,18.4) -54.7,18.4 -54,17.7 -54,12.7 v1(-50.831,9.531)
J2_PIN5: J2.5 J4.4 TP33.1 | length 37.8
  Bottom Layer w0.203: J4.4 -70.8,19.3 -68.561,19.3 -64.342,23.519 -53.458,23.519 -48.139,18.2 -45.606,18.2 -44.9,17.494 -44.9,15.38 J2.5 -43.6,14.08 TP33.1
MISO: J3.1 J5.7 TP43.1 | length 167.2
  Top Layer w0.203: J5.7 -154.525,23.175 -147.693,30.007 -28.807,30.007 -26.1,27.3 -26.1,19.2 -25.1,18.2 -21.4,18.2 -20.9,17.7 -20.9,16 -21.5,15.4 -26,15.4 J3.1
  Bottom Layer w0.203: TP43.1 -29.098,13.5 -28.449,14.149 -27.349,14.149 J3.1 J3.1@-28,14.1
MOSI: J3.6 TP37.1 U4.3 | length 117.4
  Top Layer w0.203: U4.3 -121.545,21.3 v1(-119.8,21.3) -119.3,21.3 -118.662,21.938 -118.662,27.016 -116.052,29.626 -29.026,29.626 -26.5,27.1 -26.5,19 -25.3,17.8 -23.38,17.8 J3.6
  Bottom Layer w0.203: v1(-119.8,21.3) TP37.1
NetC2_2: C2.2 TP3.1 U1.5 | length 6.4
  Top Layer w0.203: U1.5 -97.7,21.5 -97.553,21.647 -97.553,24.597 C2.2 v1(-97.55,25.85)
  Bottom Layer w0.203: v1(-97.55,25.85) TP3.1@-97.55,27.35
NetC3_2: C3.2 R2.1 TP8.1 | length 4.7
  Top Layer w0.203: v1@-107.2,19.7 C3.2 -106.25,20.85 -106.1,21 R2.1
  Bottom Layer w0.203: TP8.1 v1@-107.2,19.7
  other v1: -107.1,19.6
NetC4_2: C4.2 R2.2 TP7.1 U1.7 | length 7.4
  Top Layer w0.203: v1(-103.35,24.45) C4.2 R2.2 U1.7
  Bottom Layer w0.203: v1(-103.35,24.45) -103.35,25.95 TP7.1
NetC7_2: C7.2 R9.1 TP46.1 U3.7 U3.8 | length 9.2
  Top Layer w0.203: v1(-77.55,-2.15) C7.2 R9.1 -74.3,-2.975 -73.975,-3.3 -73.5,-3.3 -73.225,-3.575 U3.7 ; U3.8 -73.875,-3.4
  Bottom Layer w0.203: v1(-77.55,-2.15) -77.5,-2.1 TP46.1
NetC9_1: C9.1 J6.22 TP53.1 | length 5.8
  Top Layer w0.254: C9.1 -85.7,-4.7 -85.323,-5.077 J6.22 -85.323,-7.377 v1(-85.2,-7.5)
  Bottom Layer w0.254: v1(-85.2,-7.5) -84.5,-8.2 TP53.1
NetD1_1: D1.1 LS1.3 LS1.4 Q4.3 TP36.1 | length 17.1
  Top Layer w0.203: D1.1 -59.65,-3.95 -59.15,-4.45 Q4.3
  Top Layer w0.508: LS1.4@-65.5,2.7 v1(-61.5,2.7) ; D1.1 -59.65,-0.65 -61.5,1.2 v1(-61.5,2.7) ; LS1.3@-58.5,2.7 v1(-61.5,2.7)
  Bottom Layer w0.508: v1(-61.5,2.7) TP36.1
NetJ2_1: J2.1 R8.1 TP35.1 | length 32
  Top Layer w0.203: v1(-59.45,-10.25) R8.1 -56.65,-10.25 -56.106,-9.706 -56.106,6.694 J2.1
  Bottom Layer w0.203: v1(-59.45,-10.25) -59.4,-10.3 TP35.1
NetJ2_3: J2.3 J4.6 TP34.1 | length 32.6
  Bottom Layer w0.203: J4.6 -69.182,18.14 -64.184,23.138 -53.616,23.138 -48.224,17.747 -47.806,17.747 -47.4,17.341 -47.4,15.34 J2.3 -46.16,13.64 -47.3,12.5 TP34.1
NetJ2_8: J2.8 J4.5 TP30.1 | length 45.7
  Bottom Layer w0.203: J4.5 -70.72,16.9 -72.9,16.9 -73.2,17.2 -73.2,19.3 -72.74,19.76 -68.64,19.76 -64.5,23.9 -53.3,23.9 -48.1,18.7 -41.8,18.7 ; TP30.1 -41.8,19.9 -41.8,18.7 ; J2.8 -41.08,17.98 -41.8,18.7
NetJ5_1: J5.1 TP54.1 U4.4 | length 22.9
  Top Layer w0.203: J5.1 -139.6,15.6 -139.2,16 v1(-136.2,16) -136.161,16 -132.126,20.035 U4.4
  Bottom Layer w0.203: v1(-136.2,16) TP54.1
NetJ5_2: J5.2 TP49.1 U4.2 | length 29.1
  Top Layer w0.203: v3(-142.1,12.6) J5.2 -142.1,16 -141.4,16.7 -136.147,16.7 -132.431,20.416 -123.384,20.416 -123.1,20.7 -123.1,22.1 -122.625,22.575 U4.2
  Bottom Layer w0.203: TP49.1 -142.2,12.5 v3(-142.1,12.6)
NetJ5_5: J5.5 TP48.1 U4.6 | length 37.7
  Top Layer w0.203: J5.5 -149.6,12.9 -149.5,12.8 -143.2,12.8 -142.4,12 -141.435,12 -140.635,12.8 -136.2,12.8 -135.621,13.379 -135.621,15.879 -131.9,19.6 -123.3,19.6 -122.8,19.1 v1(-122.8,17.5) -122.795,17.495 U4.6
  Bottom Layer w0.203: TP48.1 v1(-122.8,17.5)
NetJ6_6: J6.6 R12.1 TP50.1 | length 4.8
  Top Layer w0.203: J6.6 -93.323,-4.923 -93.03,-4.63 -92.33,-4.63 -92.2,-4.5 R12.1
  Bottom Layer w0.203: v1(-93.2,-4.7) TP50.1
NetJ6_9: J6.9 TP55.1 U4.10 | length 59.5
  Top Layer w0.203: U4.10 v1(-114.286,16.225) -112.269,14.208 -112.269,-10.792 -110.042,-13.019 -92.2,-13.019 -91.823,-12.642 J6.9
  Bottom Layer w0.203: v1(-114.286,16.225) -113.675,16.225 TP55.1
NetJ6_13: J6.13 R10.1 TP11.1 U2.8 U3.6 | length 51.8
  Top Layer w0.203: J6.13 -89.823,-10.077 -88.9,-11 -79.761,-11 -74.8,-6.039 -74.8,-6 ; U2.8 -83,8.6 -82.472,8.072 -82.472,4.272 -82.228,4.028 -78.688,4.028 -78.172,3.512 -78.172,-3.128 -77.928,-3.372 -75.628,-3.372 -74.8,-4.2 -74.8,-6 ; R10.1 -72.175,-2.875 -72.525,-3.225 v1(-72.575,-3.225) U3.6 -72.575,-5.575 -73,-6 -74.8,-6
  Bottom Layer w0.203: TP11.1 -73.3,-2.5 v1(-72.575,-3.225)
NetJ6_14: J6.14 R11.1 R13.1 TP10.1 U2.9 U3.5 | length 55
  Top Layer w0.203: R13.1 -90.1,-4.4 -89.323,-5.177 J6.14 -89.323,-9.977 -88.681,-10.619 -79.918,-10.619 -76,-6.701 v1(-76,-4.6) -76,-4.153 -76.4,-3.753 -77.714,-3.753 -77.742,-3.781 -78.058,-3.781 -78.553,-3.286 -78.553,3.314 -78.886,3.647 -82.014,3.647 -82.042,3.619 -82.358,3.619 -82.853,4.114 -82.853,6.5 -82.853,7.753 -83.2,8.1 U2.9 ; U3.5 -71.925,-3.625 -71.6,-3.3 v1(-71.1,-3.3) -70.4,-3.3 -70.1,-3 R11.1
  Bottom Layer w0.203: v1(-76,-4.6) -71.7,-4.6 -71.1,-4 v1(-71.1,-3.3) TP10.1
NetJ6_15: J6.15 R13.2 TP51.1 | length 7.9
  Top Layer w0.203: v1(-90.1,-0.7) R13.2 -89.25,-1.75 -89.1,-1.9 -89.1,-2.98 -89.096,-2.984 -89.096,-4.316 -89.1,-4.32 -89.1,-4.6 -88.823,-4.877 J6.15
  Bottom Layer w0.203: v1(-90.1,-0.7) TP51.1
NetJ6_21: J6.21 R14.2 TP52.1 | length 5.7
  Top Layer w0.254: R14.2 -88,-4.5 -87.7,-4.8 v1(-86.9,-4.8) -86.246,-4.8 -85.823,-5.223 J6.21
  Bottom Layer w0.254: v1(-86.9,-4.8) TP52.1
NetL1_2: L1.2 TP4.1 U1.1 | length 9.8
  Top Layer w0.203: U1.1 -97.6,19.5 -97,18.9
  Top Layer w0.508: -97,18.9 L1.2 v1(-93.5,15.5)
  Bottom Layer w0.508: v1(-93.5,15.5) TP4.1
NetQ1_1: Q1.1 R5.2 TP18.1 | length 4.9
  Top Layer w0.203: R5.2 -75.75,10.85 -75.3,11.3 Q1.1 v1(-73.5,11.3)
  Bottom Layer w0.203: v1(-73.5,11.3) TP18.1
NetQ1_3: Q1.3 R15.1 R16.1 R17.1 R18.1 TP19.1 | length 21.7
  Top Layer w0.508: Q1.3 -72.45,13.05 -71.4,14.1 -68.6,14.1 -67.8,14.9 -67.8,17.9 -67.303,18.397 R18.1 R17.1 R16.1 R15.1 v3(-67.297,24.697)
  Bottom Layer w0.508: TP19.1 -68.797,24.697 v3(-67.297,24.697)
NetQ2_1: Q2.1 R6.2 TP17.1 | length 4.4
  Top Layer w0.203: R6.2 -75.1,7.8 -74.9,8 -74.9,8.4 -74.7,8.6 Q2.1 v1(-73.5,8.6)
  Bottom Layer w0.203: v1(-73.5,8.6) TP17.1
NetQ2_3: Q2.3 R19.1 R20.1 R21.1 R22.1 TP20.1 | length 30.7
  Top Layer w0.508: Q2.3 -72.45,8.556 -71.6,9.406 -71.6,12.7 -71,13.3 -68.3,13.3 ; v3(-67.7,12.7) -68.3,13.3 ; R19.1 R20.1 R21.1 R22.1 -58.8,17.3 -59.2,16.9 -66.5,16.9 -67,16.4 -67,14.6 -68.3,13.3
  Bottom Layer w0.508: TP20.1 v3(-67.7,12.7)
NetQ3_1: Q3.1 R7.2 TP16.1 | length 3.9
  Top Layer w0.203: R7.2 -75.1,5.6 -74.9,5.8 Q3.1 v1(-73.5,5.8)
  Bottom Layer w0.203: v1(-73.5,5.8) TP16.1
NetQ3_3: Q3.3 R23.1 R24.1 R25.1 R26.1 TP21.1 | length 28.7
  Top Layer w0.508: Q3.3 -72.45,6.15 -70.7,7.9 -70.7,11 -70.4,11.3 -66.2,11.3 -65.75,11.75 ; R25.1 R26.1 -65.75,11.75 ; v3(-62.6,12.2) -62.6,12 -62.6,11.3 ; R23.1 R24.1 -58.75,11.75 -59.2,11.3 -62.6,11.3 ; -65.75,11.75 -65.3,11.3 -62.6,11.3
  Bottom Layer w0.508: TP21.1 -62.6,12 v3(-62.6,12.2)
NetQ4_1: Q4.1 R8.2 TP47.1 | length 4.8
  Top Layer w0.203: Q4.1 -59.65,-7.25 -59.7,-7.3 v1(-59.7,-8) -59.35,-8.35 R8.2
  Bottom Layer w0.203: v1(-59.7,-8) TP47.1
NetR1_1: R1.1 TP2.1 U1.4 | length 7
  Top Layer w0.203: U1.4 -97.5,21 -97.1,21.4 -97.1,22.8 -96.8,23.1 -96.1,23.1 v2(-95.85,23.35) R1.1
  Bottom Layer w0.203: v2(-95.85,23.35) TP2.1@-95.85,24.85 ; TP2.1@-95.85,25.05 TP2.1@-95.8,25.1
NetR3_1: R3.1 R4.2 TP6.1 U1.8 | length 7.1
  Top Layer w0.203: R3.1 -103.4,17.6 -103.25,17.75 R4.2 -103.25,19.65 -103,19.9 -102.4,19.9 v2(-102.051,20.249) -101.8,20.5 U1.8
  Bottom Layer w0.203: TP6.1 -102.1,20.2 v2(-102.051,20.249)
NetR5_1: R5.1 TP13.1 U2.1 | length 8
  Top Layer w0.203: v1(-81.5,7.6) U2.1 ; v1(-78.7,10) R5.1
  Bottom Layer w0.203: v1(-81.5,7.6) -81.5,8.2 -79.7,10 v1(-78.7,10) TP13.1
NetR6_1: R6.1 TP14.1 U2.2 | length 4.1
  Top Layer w0.203: U2.2 v1(-78.8,8.1) -78.5,7.8 R6.1
  Bottom Layer w0.203: v1(-78.8,8.1) TP14.1
NetR7_1: R7.1 TP15.1 U2.3 | length 10.4
  Top Layer w0.203: U2.3 -81.7,8.6 -82.091,8.209 -82.091,5.991 v1(-81.7,5.6) R7.1
  Bottom Layer w0.203: TP15.1 v1(-81.7,5.6)
RED1: D2.2 R15.2 TP61.1 | length 86.7
  Top Layer w0.254: R15.2 -61.503,24.697 -59.6,26.6 v3(-32.7,26.6) ; v3(-24.3,26.6) -23.6,26.6 -22.7,27.5 -12.9,27.5 -10.2,24.8 -10.2,5.9 -11.8,4.3 -16.4,4.3 -16.9,3.8 D2.2
  Bottom Layer w0.254: v3(-32.7,26.6) v3(-24.3,26.6) ; TP61.1 -24.3,27 v3(-24.3,26.6)
RED2: D3.2 R16.2 TP64.1 | length 85.4
  Top Layer w0.254: R16.2 -62.803,22.597 -59.5,25.9 v3(-31.8,25.9) ; v3(-21.8,25.9) -13.4,25.9 -11.7,24.2 -11.7,6.5 -12.4,5.8 -17.3,5.8 -20.9,2.2 D3.2
  Bottom Layer w0.254: v3(-31.8,25.9) v3(-21.8,25.9) -21.8,27.2 TP64.1
RED3: D4.2 R17.2 TP67.1 | length 39.6
  Top Layer w0.254: R17.2 -63.028,20.497 v3(-62.9,20.369) ; v1(-48.895,10.995) -41.7,3.8 -39.4,3.8 -38.7,3.1 D4.2
  Bottom Layer w0.254: TP67.1 -63.6,21.069 -63.028,20.497 -62.764,20.497 -62.157,21.105 -53.505,21.105 -52.5,20.1 -52.5,15.718 ; -52.5,15.717 -52.5,14.6 v1(-48.895,10.995)
RED4: D5.2 R18.2 TP70.1 | length 33.8
  Top Layer w0.254: R18.2 v3(-63.028,18.397) ; v1(-50.225,10.025) -42.7,2.5 D5.2
  Bottom Layer w0.254: TP70.1 -64.597,18.397 v3(-63.028,18.397) -62.225,19.2 -54.8,19.2 -53.5,17.9 -53.5,13.3 v1(-50.225,10.025)
RESET: J2.7 TP32.1 U4.9 | length 124.3
  Top Layer w0.203: U4.9 v1(-114.7,14.955) -113.555,14.955 -112.65,14.05 -112.65,-10.95 -110.2,-13.4 -57.501,-13.4 -54.9,-10.799 -54.9,6.284 -49.184,12 -47.5,12 -47.024,12.476 -42.704,12.476 J2.7
  Bottom Layer w0.203: TP32.1 v1(-114.7,14.955)
S_E1: E1.B J3.3 TP42.1 | length 11.8
  Top Layer w0.203: E1.B -26.2,7.3 -26.2,9.6 -24.76,11.04 J3.3
  Bottom Layer w0.203: TP42.1 -25.4,12.46 -24.76,13.1 J3.3
S_E2: E1.A J3.5 TP41.1 | length 22.3
  Top Layer w0.203: E1.A -31.5,4.6 -23.1,4.6 -22.2,5.5 -22.2,14.08 J3.5
  Bottom Layer w0.203: J3.5 -22.22,13.22 -22.02,13.02 TP41.1
S_EC: E1.E J2.2 TP31.1 | length 29.2
  Top Layer w0.203: J2.2 -47.44,17.9 -42.8,17.9 -42.4,17.5 -42.4,16.2 -41.7,15.5 -35.9,15.5 -30.3,9.9 -28.2,9.9 -27.7,9.4 E1.E
  Bottom Layer w0.203: TP31.1 -50.26,16.64 J2.2
SCK: J3.2 TP39.1 U4.7 | length 117
  Top Layer w0.203: U4.7 -121.525,16.2 v1(-119.8,16.2) -119.8,17.9 -119.2,18.5 -119.2,20.1 -117.9,21.4 -117.9,26.7 -117.861,26.7 -115.697,28.864 -29.47,28.864 -27.3,26.694 J3.2
  Bottom Layer w0.203: TP39.1 v1(-119.8,16.2)
SCL5: J2.6 TP44.1 U3.3 | length 57.6
  Top Layer w0.203: U3.3 v1(-72.575,-9.275) -72.575,-10.725 -70.3,-13 -57.7,-13 -55.3,-10.6 -55.3,6.422 -49.322,12.4 -47.9,12.4 -47.4,12.9 -45.3,12.9 -44.9,13.3 -44.9,15.36 J2.6
  Bottom Layer w0.203: TP44.1 -74.075,-9.275 v1(-72.575,-9.275)
SD_CARDDETECT: J3.7 J5.10 TP40.1 | length 182.9
  Top Layer w0.203: v3(-163.8,2.8) -163,3.6 ; J5.10 -162.2,2.8 -163,3.6 ; J3.7 -18.5,15.28 -18.5,18 -19.1,18.6 -24.937,18.6 -25.7,19.363 -25.7,27.5 -28.588,30.388 -147.912,30.388 -163,15.3 -163,3.6
  Bottom Layer w0.203: v3(-163.8,2.8) TP40.1
SDA5: J2.4 TP45.1 U3.4 | length 60.1
  Top Layer w0.203: v1(-71.7,-9.3) -71.8,-9.3 -71.925,-9.175 U3.4 -71.925,-6.925 -71.746,-6.746 -70.446,-6.746 -67.9,-4.2 -61,-4.2 -60.3,-4.9 -60.3,-11 -59.9,-11.4 -56.7,-11.4 -55.7,-10.4 -55.7,6.561 -49.461,12.8 -48.215,12.8 -47.734,13.281 -47.719,13.281 -47.4,13.6 -47.4,15.4 J2.4 J2.4@-46.04,16.64
  Bottom Layer w0.203: v1(-71.7,-9.3) TP45.1
SS: J3.4 TP38.1 U4.5 | length 116.5
  Top Layer w0.203: U4.5 v1(-119.8,18.765) -119.8,20.1 -118.281,21.619 -118.281,26.858 -115.894,29.245 -29.245,29.245 -26.9,26.9 -26.9,18.78 J3.4
  Bottom Layer w0.203: v1(-119.8,18.765) -119.765,18.8 TP38.1
pads on no net: D1.2 E1.0 Fid1. Fid2. Fid3. Fid4. H5.0 H6.0 J5.0 J5.8 J5.9 J6.0 J6.4 SP1.0 SP2.0 SP3.0 SP4.0 U1.9 U2.4 U4.12 U4.13 U4.15 U4.16
copper on no net: | length 868
  Top Layer w0.15: -170,-16 -170,31 0,31 0,0 -54,0 -54,-14 -124,-14 -124,-16 -170,-16
  Bottom Layer w0.15: -170,-16 -170,31 0,31 0,0 -54,0 -54,-14 -124,-14 -124,-16 -170,-16

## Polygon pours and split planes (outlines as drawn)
GND on Top Layer "Top Layer-No Net" (solid, pour order 15): -96,-7.1 -92.4,-7.1 -92.2,-7.3 -92.2,-12.8 -98.9,-12.8 -98.9,-8.7 -96.2,-8.7 -96,-8.5
5V on Top Layer "Top Layer-No Net" (solid, pour order 17): -95.2,19.7 -96.8,19.7 -96.8,22.5 -96.6,22.7 -94.8,22.7 -94.6,22.9 -94.6,25.6 -87.3,25.6 -87.3,16 -91.9,16 -91.9,21.9 -92.1,22.1 -95,22.1 -95.2,21.9
3.3V on Top Layer "Top Layer-No Net" (solid, pour order 18): -83.3,13.8 -83.3,12.5 -87.4,12.5 -87.4,9.2 -85.7,9.2 -85.7,7.3 -91.5,7.3 -91.5,-2.3 -95.7,-2.3 -95.7,-4.2 -99.8,-4.2 -99.8,5.3 -91.3,13.8
13V on Top Layer "Top Layer-No Net" (solid, pour order 19): -91.3,3.5 -91.3,7.1 -83.2,7.1 -83.2,4.1 -82.5,3.4 -82.4,3.3 -79.2,3.3 -78.9,3 -78.9,-5.5 -82,-5.5 -82,-2.1 -79.9,-2.1 -79.9,1.5 -91.3,1.5
GND on Top Layer "Top Layer-No Net" (solid, pour order 21): -91.3,1.3 -91.3,-1 -88.7,-1 -88.7,-2.3 -82.7,-2.3 -82.7,-1.2 -80.2,-1.2 -80.1,-1.3 -80.1,1.3
13V on Top Layer "Top Layer-No Net" (solid, pour order 16): -100.7,19.2 -101.5,19.2 -101.5,19.7 -102.5,19.7 -102.5,15.6 -102.7,15.4 -104.1,15.4 -104.1,13 -100.7,13
GND on Top Layer "Top Layer-No Net" (solid, pour order 22): -91.5,-7.1 -91.5,-12.8 -70.8,-12.8 -72.8,-10.8 -72.8,-10.3 -72.8,-6.3 -76.3,-6.3 -76.3,-4.3 -76.5,-4.1 -78.7,-4.1 -78.7,-5.7 -81,-5.7 -81,-8.7 -84.1,-8.7 -84.1,-7.1
GND on Top Layer "Top Layer-No Net" (solid, remove dead copper, pour order 20): -95.172,17.978 -96.772,17.978 -97.972,19.178 -98.572,19.178 -98.772,19.378 -98.772,21.578 -98.572,21.778 -98.072,21.778 -97.872,21.978 -97.872,23.478 -98.072,23.678 -98.172,23.678 -98.372,23.878 -98.372,25.578 -94.672,25.578 -94.672,28.378 -114.972,28.378 -117.066,30.478 -169.472,30.478 -169.472,-15.522 -124.472,-15.522 -124.472,-13.522 -98.472,-13.522 -98.472,-8.722 -99.172,-8.722 -99.172,-4.422 -99.972,-4.422 -99.972,5.478 -99.772,5.678 -92.072,13.278 -92.072,14.978 -95.172,14.978
5V on Top Layer "Top Layer-No Net" (solid, pour order 23): -25.798,9.599 -25.698,9.599 -24.76,11.04 -24.7,15.1 -25.7,16 -25.7,27.4 -26.7,28.4 -94.5,28.4 -94.5,22 -91.9,22 -91.9,13.9 -83.1,13.9 -83.1,12.2 -85.4,12.2 -85.4,9.9 -79.1,9.9 -79.1,7.1 -82.5,7.1 -82.5,3.9 -78.2,3.9 -78.2,-0.4 -69.3,-0.4 -69.3,-3.5 -74.3,-3.5 -74.3,-9.2 -72.2,-9.2 -72.2,-10.8 -70.548,-12.352 -57.551,-12.352 -55.753,-10.554 -55.753,6.047 -54.6,7.3 -48.8,12.8 -48.815,17.5 -47.723,17.517 -47.5,17.8 -47.44,17.8 -42.8,17.8 -42.4,17.4 -42.4,16.1 -41.6,15.3 -35.6,15.3 -29.9,9.6
GND on Top Layer "Top Layer-No Net" (solid, pour order 24): -54.3,6.4 -48.9,11.8 -47.2,11.8 -47.2,11.799 -46.9,12.099 -43.2,12.099 -40.5,14.799 -35.6,14.8 -30.4,9.6 -26.2,9.6 -24.76,11.04 -24.8,18.899 -25.4,19.499 -25.4,27.799 -28.1,30.498 -0.5,30.498 -0.5,0.5 -54.3,0.5
13V on Bottom Layer "Top Layer-No Net" (solid, pour order 26): -104.1,12.6 -104.1,14.9 -104.05,14.95 -100.7,14.95 -100.7,14.2 -92.8,6.3 -89.5,6.3 -89.5,3.8 -95.3,3.8 -95.8,4.3
5V on Bottom Layer "Top Layer-No Net" (solid, pour order 25): -39.8,15.1 -37.8,15.1 -32.2,9.5 -18,9.5 -18,14.4 -17.4,15 -14.5,15 -14.5,18.5 -18.8,18.5 -18.8,16.2 -19.2,15.8 -21.8,15.8 -21.8,18.5 -39.8,18.5
GND on Bottom Layer "Top Layer-No Net" (solid, pour order 28): -169.5,-15.5 -169.5,15.9 -143.5,15.9 -143.5,24.4 -122.3,24.4 -122.3,29.3 -87.2,29.3 -87.2,12.3 -77.7,12.3 -77.7,1.3 -75.5,1.3 -75.5,0.3 -71.3,0.3 -71.3,3.2 -74.4,3.2 -74.4,12.3 -73.3,12.3 -73.302,19.7 -68.642,19.76 -64.502,23.9 -53.302,23.9 -48.102,18.7 -40.302,18.7 -40,18.4 -40,14.9 -37.9,14.9 -32.3,9.3 -17.8,9.3 -17.8,14.76 -17.835,14.795 -17.831,14.8 -14.3,14.8 -14.3,18.7 -18.8,18.7 -18.8,30.498 -18.799,30.5 -0.5,30.5 -0.5,0.5 -54.5,0.5 -54.5,-13.5 -124.5,-13.5 -124.5,-15.5
3.3V on Bottom Layer "Top Layer-No Net" (solid, remove dead copper, pour order 27): -21.594,18.69 -21.594,15.99 -19.194,15.99 -18.994,16.19 -18.995,30.49 -169.494,30.49 -169.5,18.7 -169.5,16.1 -158.294,16.09 -143.694,16.09 -143.694,24.59 -122.494,24.59 -122.494,29.49 -86.994,29.49 -86.994,12.49 -78.394,12.49 -77.494,11.59 -77.494,1.49 -75.294,1.49 -75.294,0.49 -71.494,0.49 -71.494,2.99 -74.694,2.99 -74.694,12.49 -73.514,12.49 -73.494,12.511 -73.494,19.29 -72.887,19.898 -66.994,19.89 -62.694,24.19 -53.194,24.19 -47.894,18.89 -41.494,18.89 -41.294,18.69

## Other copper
Top Layer:
  rectangle net GND: -100.4,19 -98.8,22
  text "TOP" at -169.2,-15.2 h1.02
Bottom Layer:
  text "BOTTOM" at -163.5,-15.2 h1.02

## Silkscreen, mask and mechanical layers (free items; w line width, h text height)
Top Overlay:
  text "EXT/EXP" at -68.6,29.9 h1.02 r180
  text "EXP1" at -42.3,29.9 h1.02 r180
  text "EXP2" at -20.3,29.9 h1.02 r180
  text "UltiController rev. 2.1" at -126.4,-5 h1.02
  text "www.ultimaker.com/uc21" at -126.4,-6.651 h1.02
  text "CdB/BK/SW/RT" at -126.397,-8.427 h1.02
  text "DISPLAY" at -93.5,-12.7 h1.02
Bottom Overlay:
  drawing of 11 lines, arcs and shapes, not listed
  text "EXT/EXP" at -75.4,29.9 h1.02 r180
  text "EXP1" at -45.6,29.9 h1.02 r180
  text "EXP2" at -24,29.9 h1.02 r180
  text "1" at -74.4,13.2 h1.02
Mechanical 1:
  text ".Pcb_File_Name_No_Path" at 0,-0.5 h1.52
Mechanical 2:
  lines w0.1: -169.5,-15.5 -124.5,-15.5 -124.5,-13.5 -54.5,-13.5 -54.5,0.5 -0.5,0.5 -0.5,30.5 -169.5,30.5 -169.5,-15.5 ; -167,-13 -127,-13 -127,-11 -57,-11 -57,3 -3,3 -3,28 -167,28 -167,-13
  lines w0.2: -143.05,-17.4 -143.05,-16 ; -90.073,-15.7 -90.073,-14 ; -27,0.6 -27,2 ; -170,-16 -170,31 0,31 0,0 -54,0 -54,-14 -124,-14 -124,-16 -170,-16

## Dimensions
0,0 to -170,-16 on Mechanical 2
0,1.4 to -54,-14 on Mechanical 2
-170,-16 to -170,31 on Mechanical 2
